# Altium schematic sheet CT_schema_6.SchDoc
size 556 x 419 mm
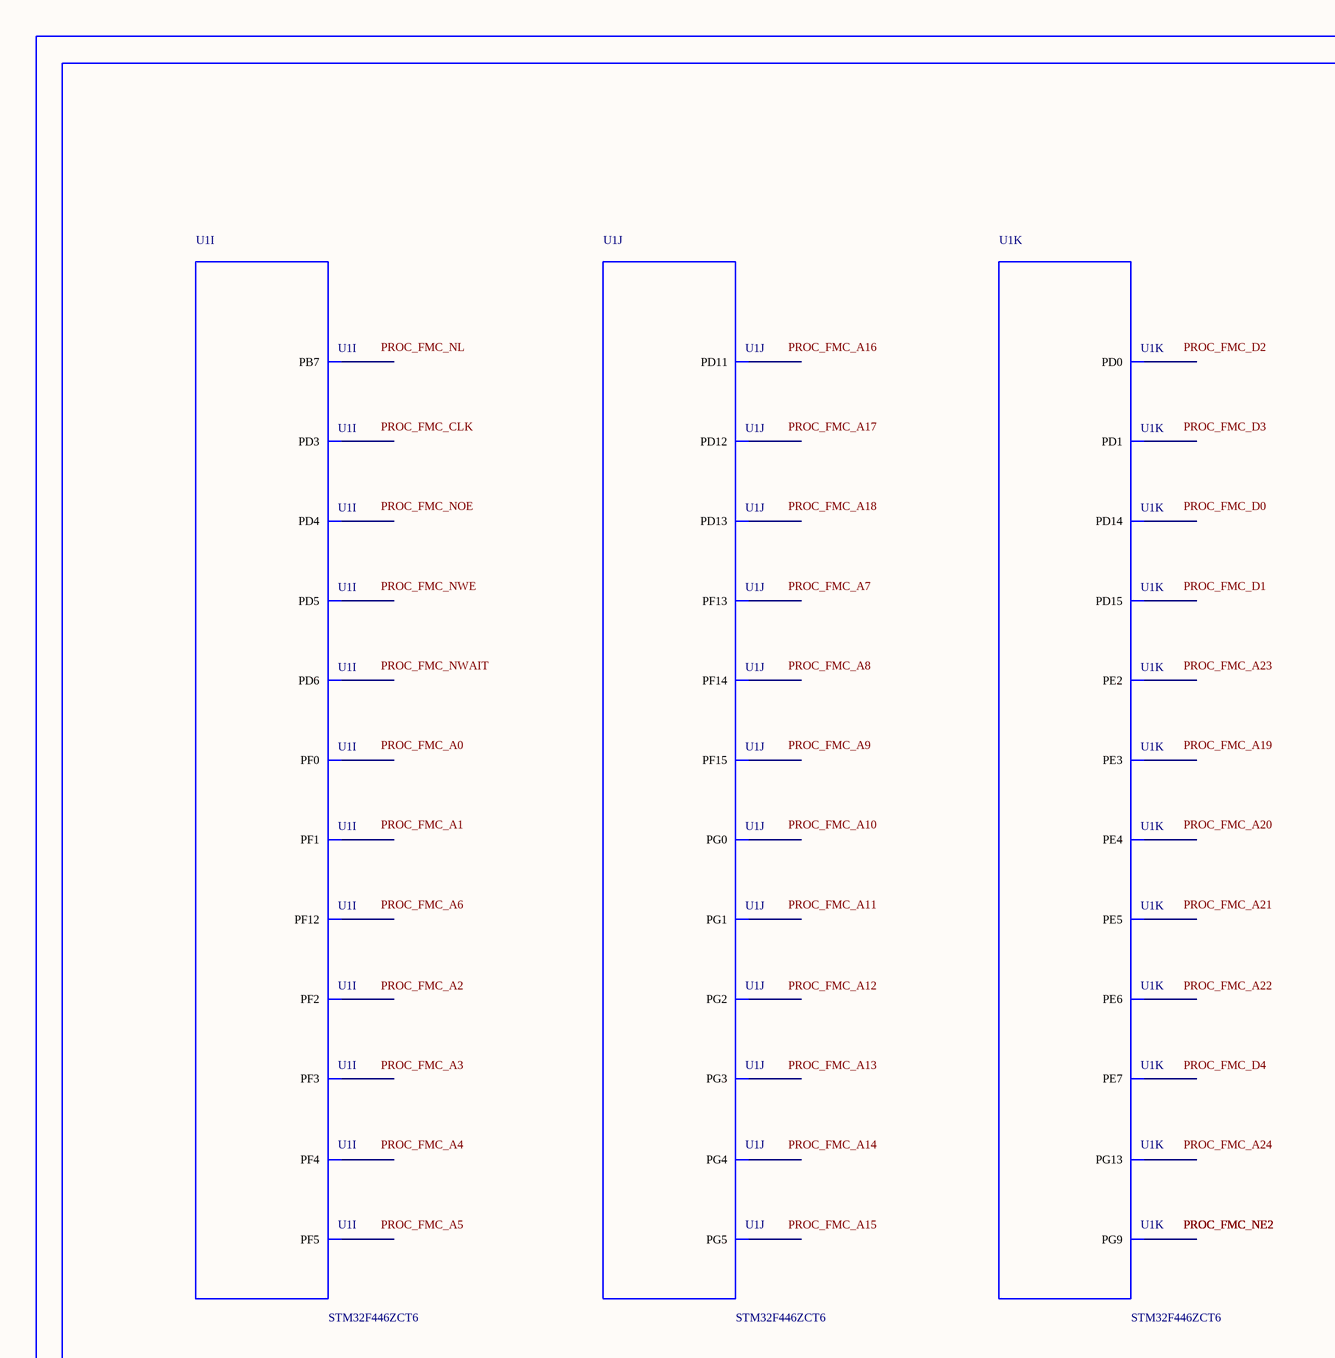
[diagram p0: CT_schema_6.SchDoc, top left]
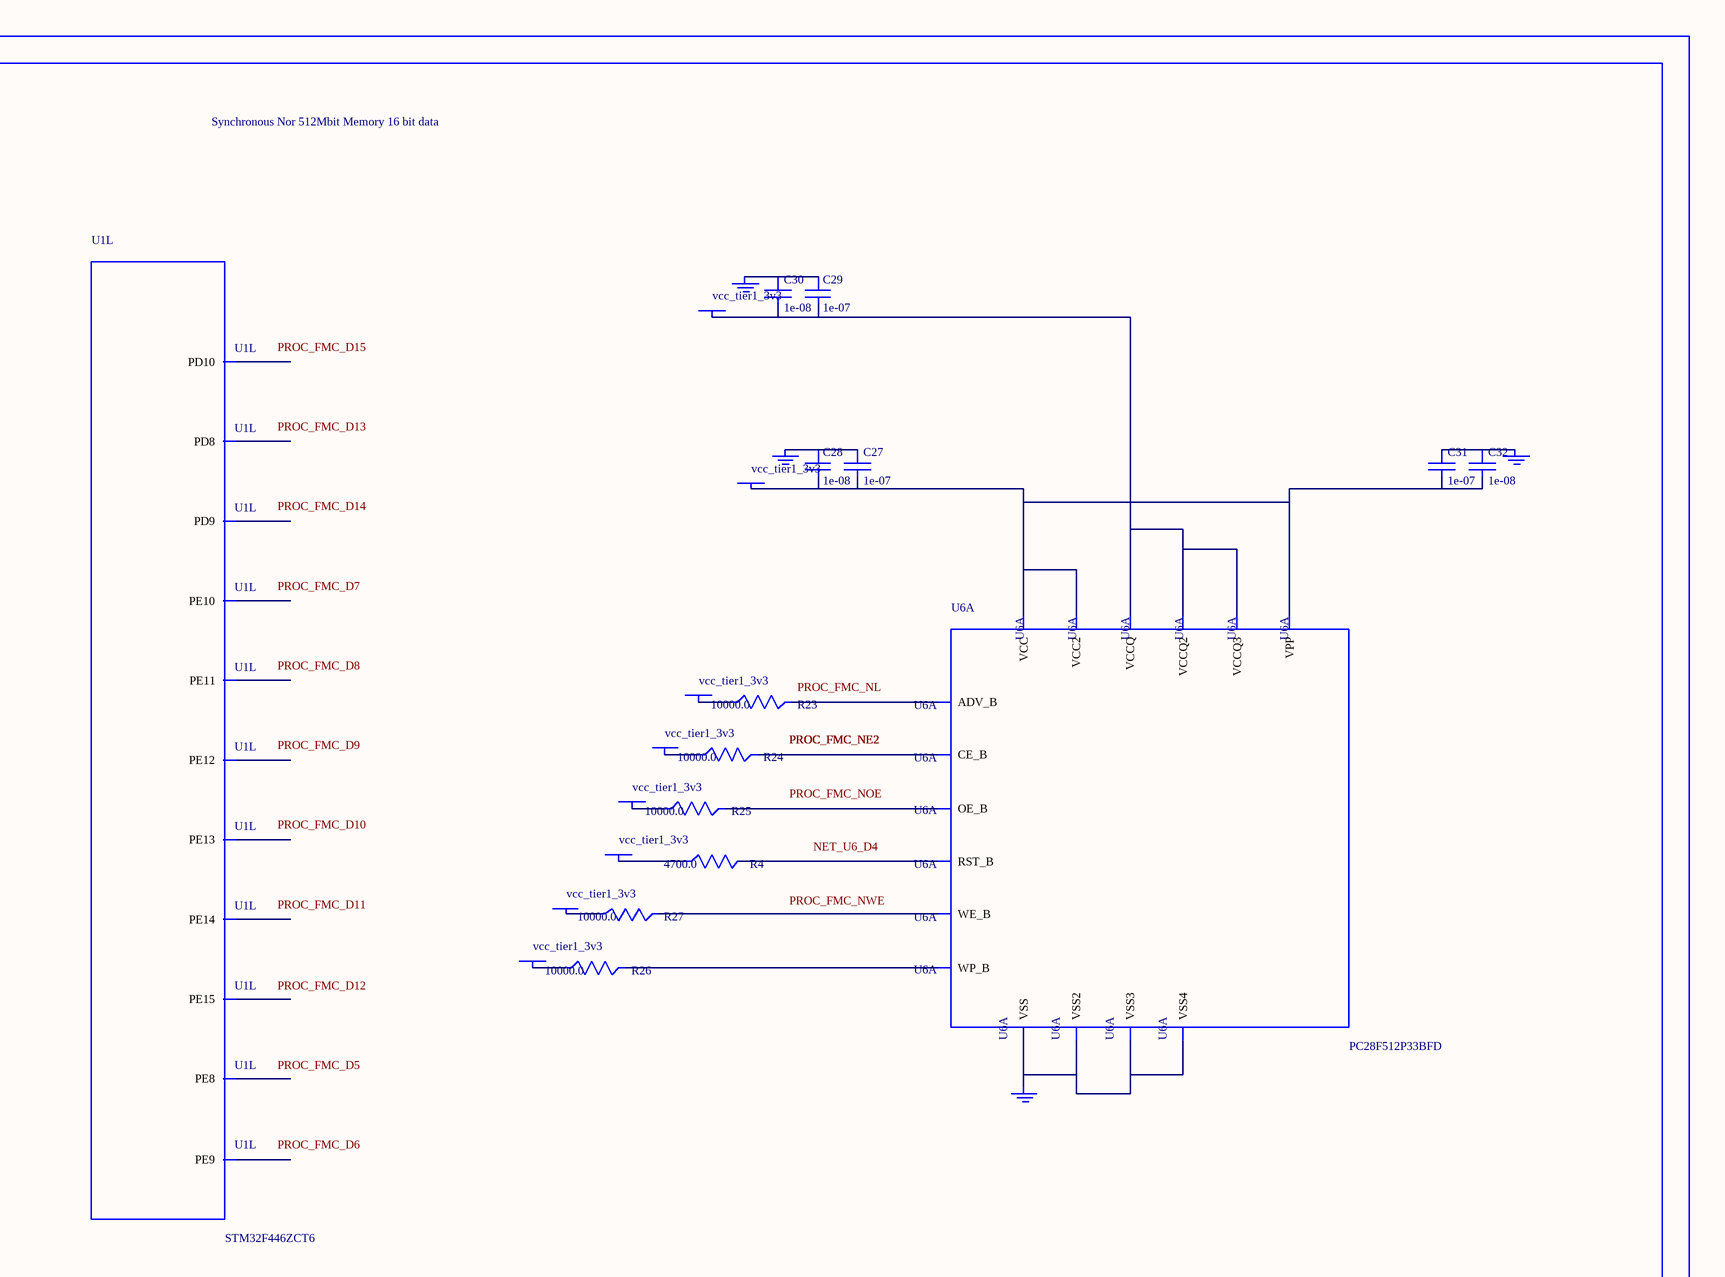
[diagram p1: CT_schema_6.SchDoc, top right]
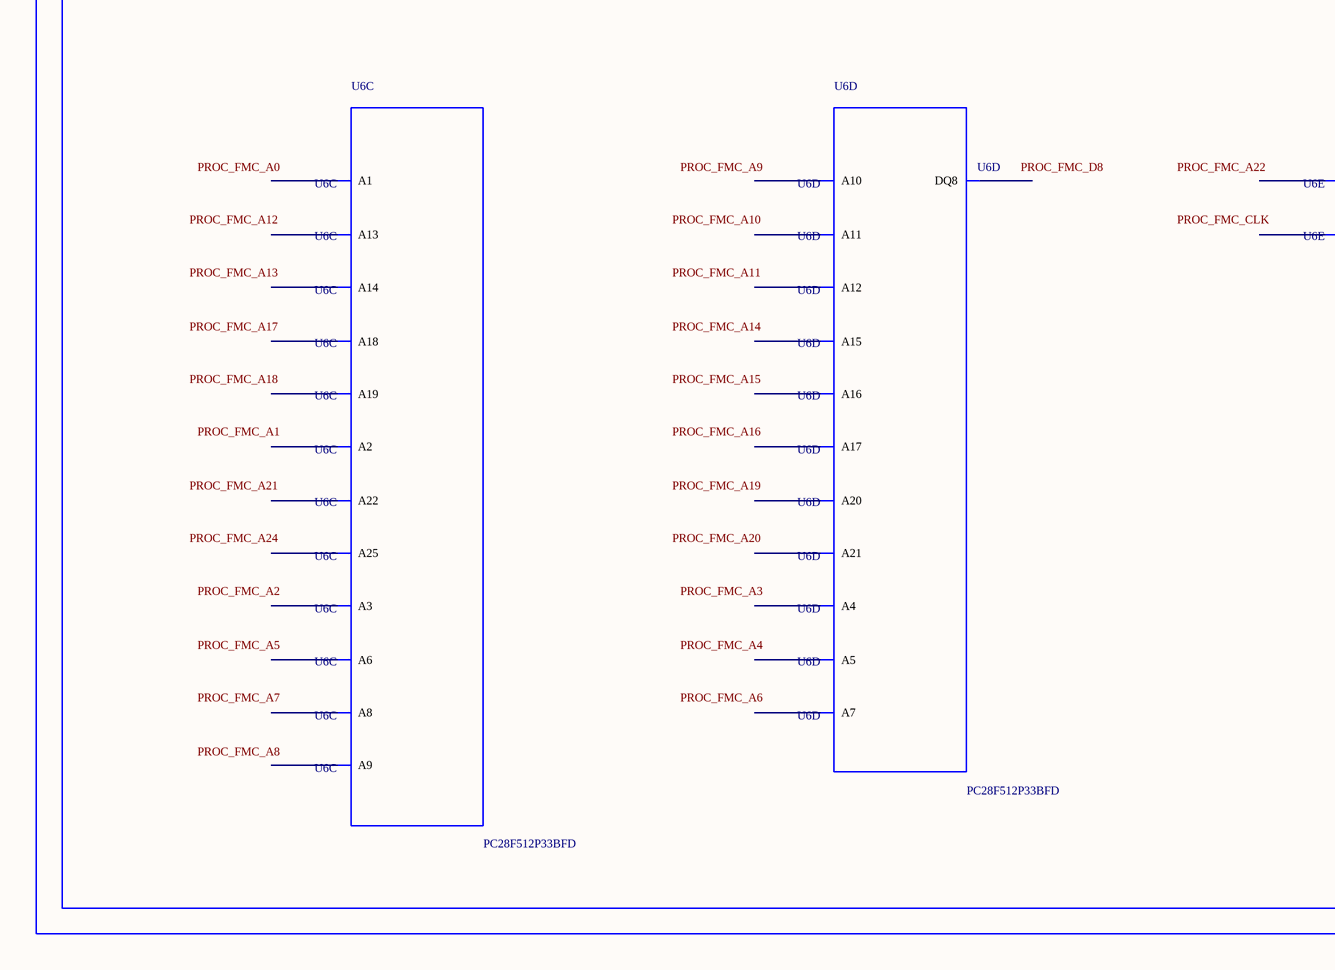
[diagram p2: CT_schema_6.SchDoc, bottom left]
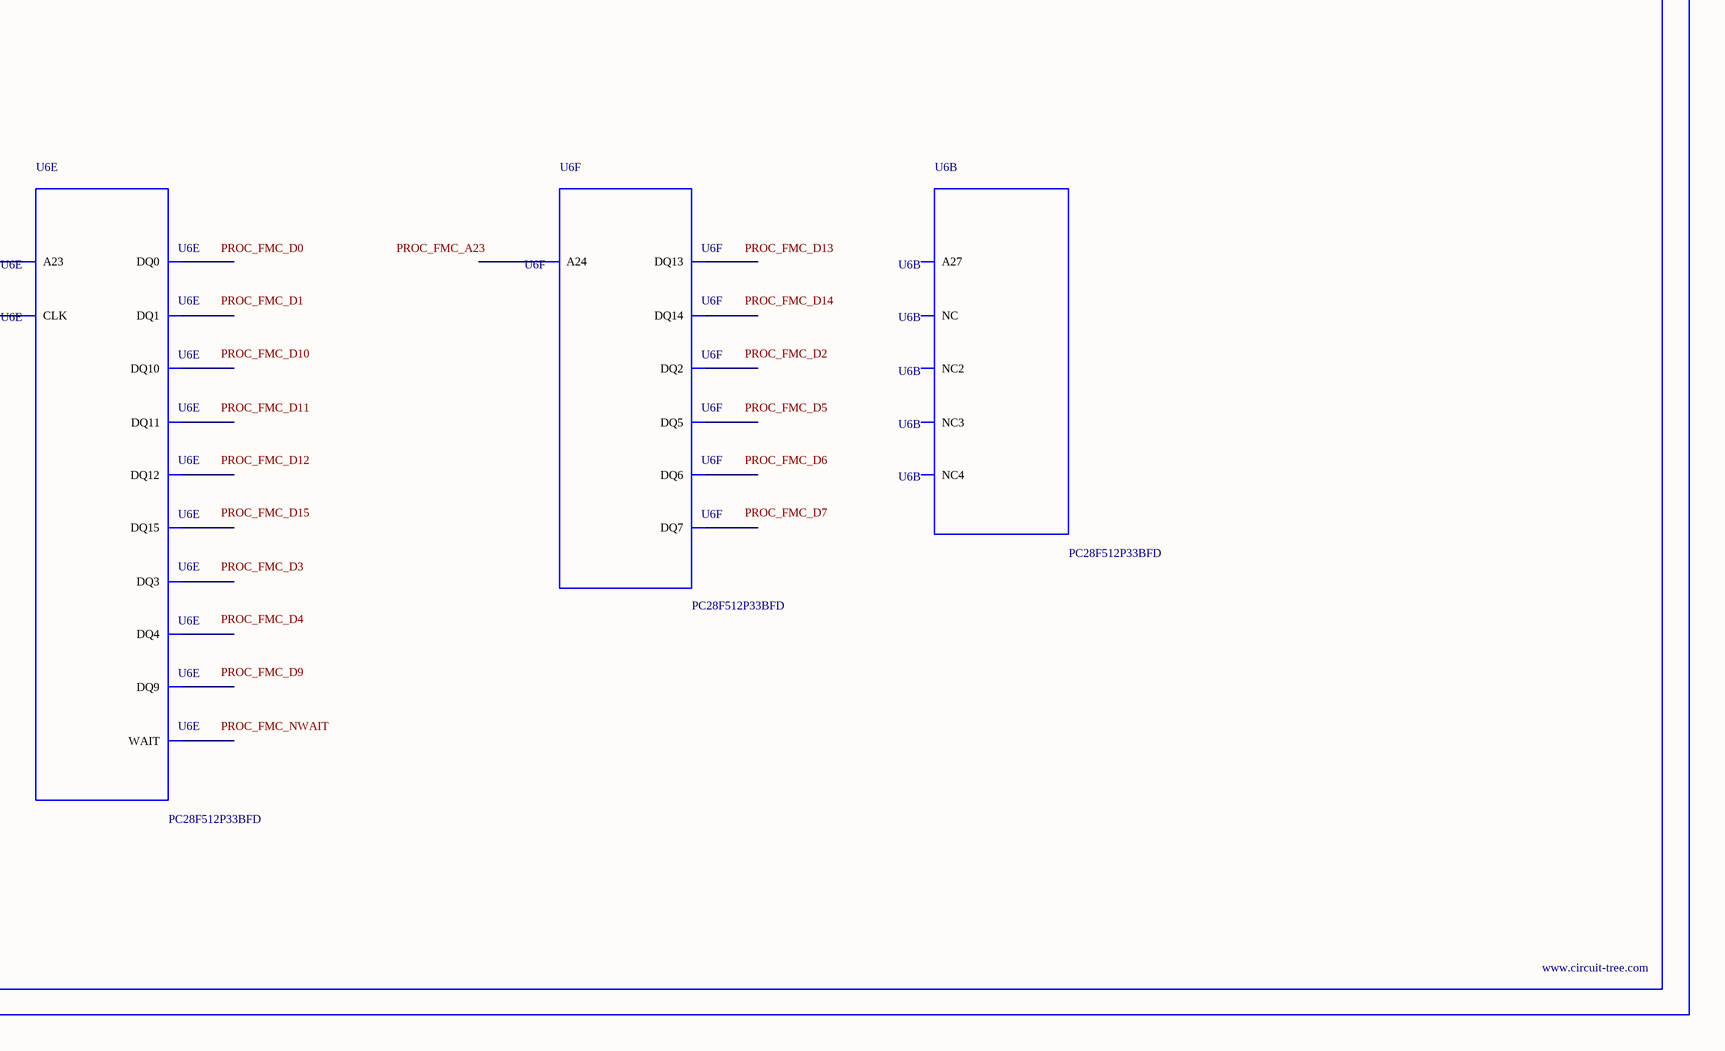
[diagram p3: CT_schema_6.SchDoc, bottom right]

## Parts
BORDER5  (no value)
C27  1e-07  [C0402]
C28  1e-08  [C0402]
C29  1e-07  [C0402]
C30  1e-08  [C0402]
C31  1e-07  [C0402]
C32  1e-08  [C0402]
GND_INSTANCE_5_0  (no value)
GND_INSTANCE_5_1  (no value)
GND_INSTANCE_5_2  (no value)
GND_INSTANCE_5_3  (no value)
POWER_INSTANCE_5_0  vcc_tier1_3v3
POWER_INSTANCE_5_1  vcc_tier1_3v3
POWER_INSTANCE_5_2  vcc_tier1_3v3
POWER_INSTANCE_5_3  vcc_tier1_3v3
POWER_INSTANCE_5_4  vcc_tier1_3v3
POWER_INSTANCE_5_5  vcc_tier1_3v3
POWER_INSTANCE_5_6  vcc_tier1_3v3
POWER_INSTANCE_5_7  vcc_tier1_3v3
R4  4700.0  [R0603]
R23  10000.0  [R0603]
R24  10000.0  [R0603]
R25  10000.0  [R0603]
R26  10000.0  [R0603]
R27  10000.0  [R0603]
U1  STM32F446ZCT6  [LQFP144]  (parts I,J,K,L of 12)
U6  PC28F512P33BFD  [PC28F512P33BFD]  (parts A,B,C,D,E,F of 6)

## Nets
NetC27_1: C27.1 C28.1 GND_INSTANCE_5_0.0(GND)
NetC27_2: C27.2 C28.2 C31.2 C32.2 POWER_INSTANCE_5_0.0(PWR) U6.A4(VPP) U6.A6(VCC) U6.H3(VCC2)
NetC29_1: C29.1 C30.1 GND_INSTANCE_5_1.0(GND)
NetC29_2: C29.2 C30.2 POWER_INSTANCE_5_1.0(PWR) U6.D5(VCCQ) U6.D6(VCCQ2) U6.G4(VCCQ3)
NetC31_1: C31.1 C32.1 GND_INSTANCE_5_2.0(GND)
NetGND_INSTANCE_5_3_0: GND_INSTANCE_5_3.0(GND) U6.B2(VSS) U6.H2(VSS2) U6.H4(VSS3) U6.H6(VSS4)
NetPOWER_INSTANCE_5_2_0: POWER_INSTANCE_5_2.0(PWR) R23.1
NetPOWER_INSTANCE_5_3_0: POWER_INSTANCE_5_3.0(PWR) R24.1
NetPOWER_INSTANCE_5_4_0: POWER_INSTANCE_5_4.0(PWR) R25.1
NetPOWER_INSTANCE_5_5_0: POWER_INSTANCE_5_5.0(PWR) R26.1
NetPOWER_INSTANCE_5_6_0: POWER_INSTANCE_5_6.0(PWR) R27.1
NetPOWER_INSTANCE_5_7_0: POWER_INSTANCE_5_7.0(PWR) R4.1
NetR4_2: R4.2 U6.D4(RST_B)
NetR23_2: R23.2 U6.F6(ADV_B)
NetR24_2: R24.2 U6.B4(CE_B)
NetR25_2: R25.2 U6.F8(OE_B)
NetR26_2: R26.2 U6.C6(WP_B)
NetR27_2: R27.2 U6.G8(WE_B)

Not connected (* = marked no-connect by the designer): U1 1(PE2) 2(PE3) 3(PE4) 4(PE5) 5(PE6) 10(PF0) 11(PF1) 12(PF2) 13(PF3) 14(PF4) 15(PF5) 50(PF12) 53(PF13) 54(PF14) 55(PF15) 56(PG0) 57(PG1) 58(PE7) 59(PE8) 60(PE9) 63(PE10) 64(PE11) 65(PE12) 66(PE13) 67(PE14) 68(PE15) 77(PD8) 78(PD9) 79(PD10) 80(PD11) 81(PD12) 82(PD13) 85(PD14) 86(PD15) 87(PG2) 88(PG3) 89(PG4) 90(PG5) 114(PD0) 115(PD1) 117(PD3) 118(PD4) 119(PD5) 122(PD6) 124(PG9) 128(PG13) 137(PB7); U6 A1 A2(A6) A3(A8) A5(A13) A7(A18) A8(A22) B1(A2) B3(A9) B5(A14) B6(A25) B7(A19) B8(NC) C1(A3) C2(A7) C3(A10) C4(A12) C5(A15) C7(A20) C8(A21) D1(A4) D2(A5) D3(A11) D7(A16) D8(A17) E1(DQ8) E2(DQ1) E3(DQ9) E4(DQ3) E5(DQ4) E6(CLK) E7(DQ15) E8(NC2) F1(NC3) F2(DQ0) F3(DQ10) F4(DQ11) F5(DQ12) F7(WAIT) G1(A23) G2(NC4) G3(DQ2) G5(DQ5) G6(DQ6) G7(DQ14) H1(A27) H5(DQ13) H7(DQ7) H8(A24)

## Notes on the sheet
- Labels drawn without touching a wire or pin: NET_U6_D4, PROC_FMC_A0, PROC_FMC_A1, PROC_FMC_A2, PROC_FMC_A3, PROC_FMC_A4, PROC_FMC_A5, PROC_FMC_A6, PROC_FMC_A7, PROC_FMC_A8, PROC_FMC_A9, PROC_FMC_A10, PROC_FMC_A11, PROC_FMC_A12, PROC_FMC_A13, PROC_FMC_A14, PROC_FMC_A15, PROC_FMC_A16, PROC_FMC_A17, PROC_FMC_A18, PROC_FMC_A19, PROC_FMC_A20, PROC_FMC_A21, PROC_FMC_A22, PROC_FMC_A23, PROC_FMC_A24, PROC_FMC_CLK, PROC_FMC_D0, PROC_FMC_D1, PROC_FMC_D2, PROC_FMC_D3, PROC_FMC_D4, PROC_FMC_D5, PROC_FMC_D6, PROC_FMC_D7, PROC_FMC_D8, PROC_FMC_D9, PROC_FMC_D10, PROC_FMC_D11, PROC_FMC_D12, PROC_FMC_D13, PROC_FMC_D14, PROC_FMC_D15, PROC_FMC_NL, PROC_FMC_NOE, PROC_FMC_NWAIT, PROC_FMC_NWE

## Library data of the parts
BORDER5 = BORDER_PAGE5
C27 C29 C31 = C0402C104K3RACTU
C28 C30 C32 = C0402C103K3RAC
GND_INSTANCE_5_0-GND_INSTANCE_5_3 = GND
POWER_INSTANCE_5_0-POWER_INSTANCE_5_7 = PWR
R4 = RC0603JR-074K7L
R23-R27 = RC0603JR-0710KL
